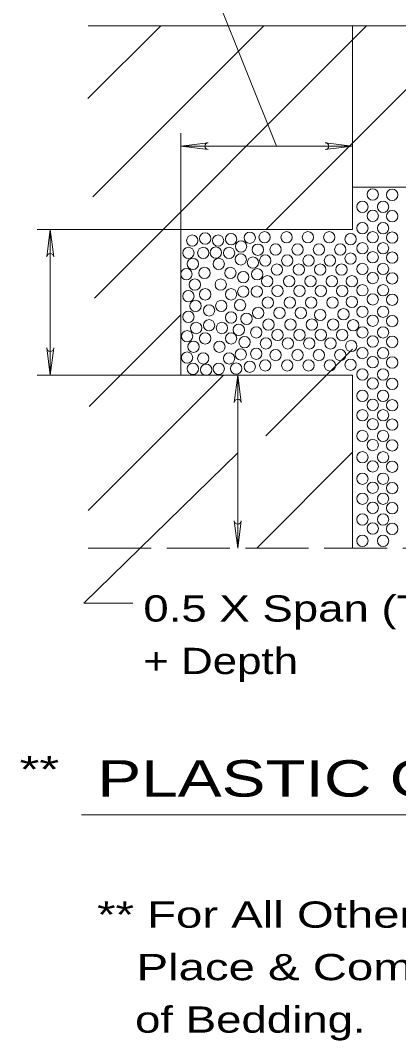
# Model space of a CAD drawing. Extents: x 750.7 to 784.7, y 834.8 to 878.8.
# Drawn here: x 773.06 to 775.66, y 845.68 to 852.67 of the extents above; entities that cross this region are included whole.
import ezdxf

# ---------------------------------------------------------------- set-up
doc = ezdxf.new("R2010")
doc.units = 0
doc.header["$LTSCALE"] = 0.072
doc.linetypes.add('LONG_DASHED', pattern=[7.5, 6, -1.5])
doc.layers.add('1', color=7, linetype='Continuous', lineweight=13)
doc.layers.add('47', color=7, linetype='Continuous', lineweight=13)

msp = doc.modelspace()

# ---------------------------------------------------------------- linework, layer by layer
at = {"layer": '1'}
for p, q in [((774.82, 851.81225), (774.35833, 852.96675)), ((773.52525, 852.13867), (774.02492, 852.63842)), ((773.52717, 852.63842), (780.6465, 852.63842)), ((773.55908, 851.46542), (774.732, 852.63842)), ((773.57125, 850.77033), (775.43908, 852.63842)), ((774.74817, 851.24025), (776.14617, 852.63842)), ((775.34258, 852.63842), (775.34258, 851.24025)), ((774.16375, 851.24025), (774.16375, 851.90108)), ((774.16375, 851.81225), (775.34258, 851.81225)), ((775.34258, 851.53025), (778.34258, 851.53025)), ((774.16375, 851.24025), (773.17767, 851.24025)), ((773.2665, 850.2405), (773.2665, 851.24025)), ((775.34258, 851.24025), (774.16375, 851.24025)), ((773.53408, 850.026), (774.16375, 850.65575)), ((774.74608, 849.824), (775.34258, 850.4205)), ((774.16375, 850.2405), (773.17767, 850.2405)), ((773.52758, 849.31242), (774.45558, 850.2405)), ((774.55367, 849.05517), (774.55367, 850.2405)), ((775.34258, 850.2405), (775.34258, 849.05517)), ((774.6845, 849.05517), (775.34258, 849.71325)), ((773.48175, 847.22583), (780.63675, 847.22583))]:
    msp.add_line(p, q, dxfattribs=at)
at = {"layer": '1', "linetype": 'LONG_DASHED'}
msp.add_line((773.52717, 849.05517), (780.6465, 849.05517), dxfattribs=at)
at = {"layer": '1'}
for points in [[(775.34258, 850.2405), (774.16375, 850.2405), (774.16375, 851.24025)], [(774.55367, 849.70758), (773.49725, 848.67742), (773.83458, 848.67742)]]:
    msp.add_lwpolyline(points, dxfattribs=at)
for centre in [(775.48116, 851.48039), (775.61433, 851.47806), (775.41013, 851.39603), (775.55216, 851.39606), (775.48116, 851.33389), (775.61433, 851.33156), (775.41013, 851.24944), (775.55216, 851.24947), (774.3303, 851.17833), (774.5078, 851.17391), (774.63647, 851.18419), (774.73855, 851.18724), (774.88947, 851.18724), (775.03597, 851.18724), (775.18239, 851.18724), (775.32889, 851.1739), (775.48116, 851.18731), (775.61433, 851.18497), (774.24147, 851.16415), (774.41897, 851.16415), (774.57656, 851.12419), (774.69197, 851.10202), (774.81397, 851.1029), (774.96489, 851.1029), (775.11139, 851.1029), (775.2578, 851.1029), (775.41013, 851.11178), (775.55216, 851.11181), (774.21481, 851.07977), (774.31689, 851.07982), (774.40347, 851.08202), (774.49439, 851.07982), (774.57431, 851.03544), (775.32889, 851.04074), (775.48116, 851.04964), (775.61433, 851.04731), (774.24589, 851.00432), (774.42339, 851.00432), (774.65864, 851.01319), (774.74297, 851.0274), (774.82289, 850.96524), (774.89389, 851.0274), (774.9738, 850.96524), (775.04039, 851.0274), (775.1203, 850.96524), (775.1868, 851.0274), (775.26672, 850.96524), (775.41013, 850.96969), (775.55216, 850.96972), (774.20155, 850.93416), (774.3258, 850.94215), (774.5033, 850.94215), (774.59206, 850.91327), (774.68756, 850.93327), (775.48116, 850.90756), (775.61433, 850.90522), (774.25922, 850.86224), (774.43672, 850.86224), (774.7563, 850.88532), (774.90722, 850.88532), (775.05372, 850.88532), (775.20014, 850.88532), (775.33772, 850.88532), (775.41013, 850.82319), (775.55216, 850.82322), (774.21488, 850.78316), (774.33022, 850.79565), (774.50772, 850.79565), (774.59213, 850.81425), (774.68538, 850.81425), (774.8273, 850.81874), (774.97822, 850.81874), (775.12472, 850.81874), (775.27114, 850.81874), (775.48116, 850.76106), (775.61433, 850.75872), (774.26364, 850.71574), (774.35688, 850.6855), (774.44114, 850.71574), (774.56997, 850.721), (774.76072, 850.73882), (774.91164, 850.73882), (775.05814, 850.73882), (775.20455, 850.73882), (775.33772, 850.74324), (774.21488, 850.64108), (774.5078, 850.63666), (774.61438, 850.62775), (774.69422, 850.66775), (774.84072, 850.66775), (774.98722, 850.66775), (775.1203, 850.65441), (775.28005, 850.6589), (775.41013, 850.67661), (775.48116, 850.61447), (775.55216, 850.67664), (775.61433, 850.61214), (774.26814, 850.56474), (774.35688, 850.58341), (774.44564, 850.56474), (774.56105, 850.55233), (774.76522, 850.58782), (774.91614, 850.58782), (775.06264, 850.58782), (775.20905, 850.58782), (775.34664, 850.5834), (774.20597, 850.50791), (774.33022, 850.49374), (774.50772, 850.49374), (774.68088, 850.53458), (774.8273, 850.51682), (774.97822, 850.51682), (775.12472, 850.51682), (775.27114, 850.51682), (775.41013, 850.53461), (775.48116, 850.47247), (775.55216, 850.53464), (775.61433, 850.47014), (774.2503, 850.43599), (774.4278, 850.43599), (774.60105, 850.46791), (774.74739, 850.45907), (774.8983, 850.45907), (775.0448, 850.45907), (775.19122, 850.45907), (775.3333, 850.44132), (774.20597, 850.36141), (774.31689, 850.35607), (774.49439, 850.35607), (774.57438, 850.38358), (774.68088, 850.388), (774.81397, 850.37915), (774.96489, 850.37915), (775.11139, 850.37915), (775.2578, 850.37915), (775.41013, 850.39253), (775.48116, 850.33039), (775.55216, 850.39256), (774.24589, 850.28499), (774.33689, 850.27835), (774.42339, 850.28499), (774.5433, 850.28591), (774.63655, 850.29925), (774.74297, 850.30807), (774.89389, 850.30807), (775.04039, 850.30807), (775.1868, 850.30807), (775.32889, 850.31257), (775.61433, 850.32806), (775.41013, 850.24603), (775.55216, 850.24606), (775.48116, 850.18389), (775.61433, 850.18156), (775.41013, 850.09944), (775.55216, 850.09947), (775.48116, 850.03731), (775.61433, 850.03497), (775.41013, 849.96628), (775.55216, 849.96631), (775.48116, 849.90414), (775.61433, 849.90181), (775.41013, 849.82419), (775.55216, 849.82422), (775.48116, 849.76206), (775.61433, 849.75972), (775.41013, 849.67769), (775.55216, 849.67772), (775.48116, 849.61556), (775.61433, 849.61322), (775.41013, 849.53111), (775.55216, 849.53114), (775.48116, 849.46897), (775.61433, 849.46664), (775.41013, 849.39344), (775.55216, 849.39347), (775.48116, 849.33131), (775.61433, 849.32897), (775.41013, 849.25136), (775.55216, 849.25139), (775.48116, 849.18922), (775.61433, 849.18689), (775.41013, 849.10486), (775.55216, 849.10489)]:
    msp.add_circle(centre, 0.03892, dxfattribs=at)
at = {"layer": '47'}
for points in [[(774.35125, 851.78883), (774.16375, 851.81225), (774.35125, 851.83567)], [(775.15508, 851.83567), (775.34258, 851.81225), (775.15508, 851.78883)], [(773.24308, 851.05275), (773.2665, 851.24025), (773.28992, 851.05275)], [(773.28992, 850.428), (773.2665, 850.2405), (773.24308, 850.428)], [(774.53025, 850.053), (774.55367, 850.2405), (774.57708, 850.053)], [(774.57708, 849.24267), (774.55367, 849.05517), (774.53025, 849.24267)]]:
    msp.add_lwpolyline(points, dxfattribs=at)
for centre, start, end in [((774.35126, 851.81226), 90, 270), ((775.15508, 851.81224), 270, 90), ((773.26651, 851.05274), 0, 180), ((773.26649, 850.42801), 180, 0), ((774.55367, 850.05299), 0, 180), ((774.55366, 849.24267), 180, 0)]:
    msp.add_arc(centre, 0.02342, start, end, dxfattribs=at)

# ---------------------------------------------------------------- texts
at = {"layer": '1'}
for s, height, width, p in [('0.5 X Span (Typ.)', 0.18, 1.3, (773.90567, 848.55075)), ('+ Depth', 0.18, 1.25, (773.90567, 848.19075)), ('**', 0.18, 1.45, (773.05567, 847.44775)), ('PLASTIC CONDUIT, TYPE C-FILL', 0.25, 1.35, (773.59017, 847.34992)), ('** For All Other Type C Conduits', 0.18, 1.35, (773.58825, 846.45075)), ('   Place & Compact Backfill on Top', 0.18, 1.35, (773.58825, 846.09075)), ('   of Bedding.', 0.18, 1.3, (773.58825, 845.73075))]:
    msp.add_text(s, height=height, dxfattribs=dict(at, width=width)).set_placement(p)

doc.saveas('drawing.dxf')
